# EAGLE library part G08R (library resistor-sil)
SIL RESISTOR
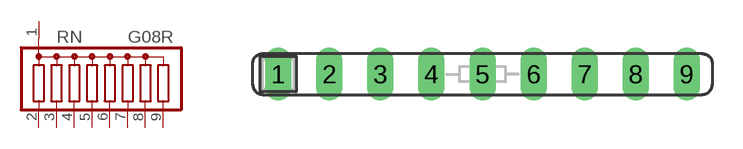
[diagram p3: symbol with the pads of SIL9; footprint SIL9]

Designator prefix RN

## G08R (OC_FARNELL: unknown; OC_NEWARK: unknown)  [SIL9]
1  1  pas
2  2  pas
3  3  pas
4  4  pas
5  5  pas
6  6  pas
7  7  pas
8  8  pas
9  9  pas

## Footprint SIL9 (pad centres in mm)
Single In Line
drill 0.813 long: 1 -10.16,0; 2 -7.62,0; 3 -5.08,0; 4 -2.54,0; 5 0,0; 6 2.54,0; 7 5.08,0; 8 7.62,0; 9 10.16,0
